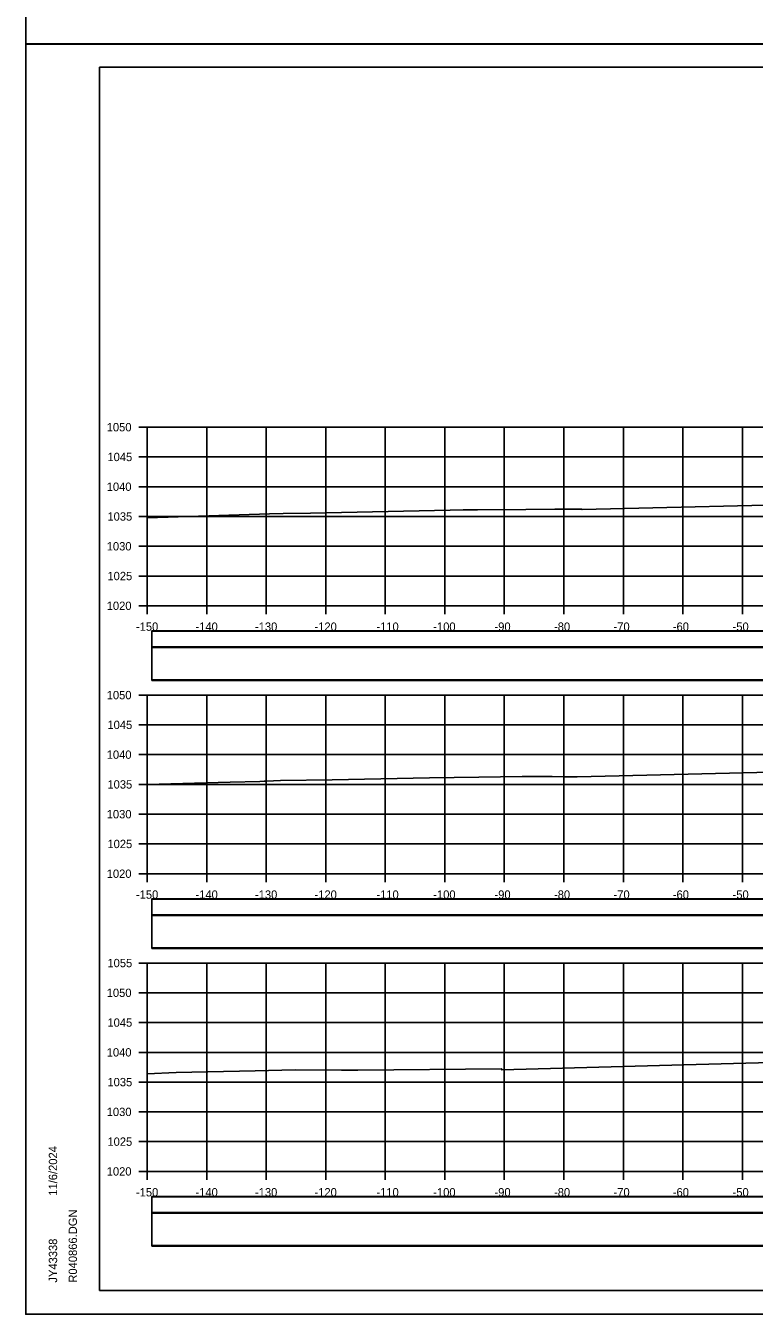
# Model space of a CAD drawing. Extents: x 1370565 to 1374448, y 301010 to 304637.
# Drawn here: x 1373198.4 to 1373320.8, y 301511.7 to 301728.1 of the extents above; entities that cross this region are included whole.
import ezdxf

# ---------------------------------------------------------------- set-up
doc = ezdxf.new("R2010")
doc.units = 0
for name, color, linetype in [('Default', 7, 'Continuous'), ('R_Axis', 7, 'Continuous'), ('R_Axis Annot', 7, 'Continuous'), ('R_Border', 7, 'Continuous'), ('R_Drive', 7, 'Continuous'), ('R_Exist Surface', 7, 'Continuous'), ('R_Grid', 7, 'Continuous'), ('R_No Plot', 7, 'Continuous')]:
    doc.layers.add(name, color=color, linetype=linetype)

msp = doc.modelspace()

# ---------------------------------------------------------------- linework, layer by layer
at = {"layer": 'Default'}
for points in [[(1373219.61, 301623.68), (1373518.02, 301623.68), (1373518.02, 301626.38), (1373219.61, 301626.38)], [(1373219.61, 301618.1), (1373518.02, 301618.1), (1373518.02, 301623.62), (1373219.61, 301623.62)], [(1373219.61, 301578.68), (1373518.02, 301578.68), (1373518.02, 301581.38), (1373219.61, 301581.38)], [(1373219.61, 301573.1), (1373518.02, 301573.1), (1373518.02, 301578.62), (1373219.61, 301578.62)], [(1373219.61, 301528.68), (1373518.02, 301528.68), (1373518.02, 301531.38), (1373219.61, 301531.38)], [(1373219.61, 301523.1), (1373518.02, 301523.1), (1373518.02, 301528.62), (1373219.61, 301528.62)]]:
    msp.add_lwpolyline(points, close=True, dxfattribs=at)
at = {"layer": 'R_Axis'}
for p, q in [((1373217.41, 301660.64), (1373218.81, 301660.64)), ((1373218.81, 301630.64), (1373218.81, 301660.64)), ((1373217.41, 301655.64), (1373218.81, 301655.64)), ((1373217.41, 301650.64), (1373218.81, 301650.64)), ((1373217.41, 301645.64), (1373218.81, 301645.64)), ((1373217.41, 301640.64), (1373218.81, 301640.64)), ((1373217.41, 301635.64), (1373218.81, 301635.64)), ((1373217.41, 301630.64), (1373218.81, 301630.64)), ((1373218.81, 301630.64), (1373518.81, 301630.64)), ((1373218.81, 301629.24), (1373218.81, 301630.64)), ((1373228.81, 301629.24), (1373228.81, 301630.64)), ((1373238.81, 301629.24), (1373238.81, 301630.64)), ((1373248.81, 301629.24), (1373248.81, 301630.64)), ((1373258.81, 301629.24), (1373258.81, 301630.64)), ((1373268.81, 301629.24), (1373268.81, 301630.64)), ((1373278.81, 301629.24), (1373278.81, 301630.64)), ((1373288.81, 301629.24), (1373288.81, 301630.64)), ((1373298.81, 301629.24), (1373298.81, 301630.64)), ((1373308.81, 301629.24), (1373308.81, 301630.64)), ((1373318.81, 301629.24), (1373318.81, 301630.64)), ((1373217.41, 301615.64), (1373218.81, 301615.64)), ((1373218.81, 301585.64), (1373218.81, 301615.64)), ((1373217.41, 301610.64), (1373218.81, 301610.64)), ((1373217.41, 301605.64), (1373218.81, 301605.64)), ((1373217.41, 301600.64), (1373218.81, 301600.64)), ((1373217.41, 301595.64), (1373218.81, 301595.64)), ((1373217.41, 301590.64), (1373218.81, 301590.64)), ((1373217.41, 301585.64), (1373218.81, 301585.64)), ((1373218.81, 301585.64), (1373518.81, 301585.64)), ((1373218.81, 301584.24), (1373218.81, 301585.64)), ((1373228.81, 301584.24), (1373228.81, 301585.64)), ((1373238.81, 301584.24), (1373238.81, 301585.64)), ((1373248.81, 301584.24), (1373248.81, 301585.64)), ((1373258.81, 301584.24), (1373258.81, 301585.64)), ((1373268.81, 301584.24), (1373268.81, 301585.64)), ((1373278.81, 301584.24), (1373278.81, 301585.64)), ((1373288.81, 301584.24), (1373288.81, 301585.64)), ((1373298.81, 301584.24), (1373298.81, 301585.64)), ((1373308.81, 301584.24), (1373308.81, 301585.64)), ((1373318.81, 301584.24), (1373318.81, 301585.64)), ((1373217.41, 301570.64), (1373218.81, 301570.64)), ((1373218.81, 301535.64), (1373218.81, 301570.64)), ((1373217.41, 301565.64), (1373218.81, 301565.64)), ((1373217.41, 301560.64), (1373218.81, 301560.64)), ((1373217.41, 301555.64), (1373218.81, 301555.64)), ((1373217.41, 301550.64), (1373218.81, 301550.64)), ((1373217.41, 301545.64), (1373218.81, 301545.64)), ((1373217.41, 301540.64), (1373218.81, 301540.64)), ((1373217.41, 301535.64), (1373218.81, 301535.64)), ((1373218.81, 301535.64), (1373518.81, 301535.64)), ((1373218.81, 301534.24), (1373218.81, 301535.64)), ((1373228.81, 301534.24), (1373228.81, 301535.64)), ((1373238.81, 301534.24), (1373238.81, 301535.64)), ((1373248.81, 301534.24), (1373248.81, 301535.64)), ((1373258.81, 301534.24), (1373258.81, 301535.64)), ((1373268.81, 301534.24), (1373268.81, 301535.64)), ((1373278.81, 301534.24), (1373278.81, 301535.64)), ((1373288.81, 301534.24), (1373288.81, 301535.64)), ((1373298.81, 301534.24), (1373298.81, 301535.64)), ((1373308.81, 301534.24), (1373308.81, 301535.64)), ((1373318.81, 301534.24), (1373318.81, 301535.64))]:
    msp.add_line(p, q, dxfattribs=at)
at = {"layer": 'R_Border'}
for p, q in [((1373210.81, 301721.1), (1373526.99, 301721.1)), ((1373210.81, 301515.64), (1373210.81, 301721.1)), ((1373210.81, 301515.64), (1373210.81, 301515.64)), ((1373526.99, 301515.64), (1373210.81, 301515.64))]:
    msp.add_line(p, q, dxfattribs=at)
at = {"layer": 'R_Drive'}
for points in [[(1373219.61, 301623.73), (1373518.02, 301623.73), (1373518.02, 301626.44), (1373219.61, 301626.44)], [(1373219.61, 301618.21), (1373518.02, 301618.21), (1373518.02, 301623.73), (1373219.61, 301623.73)], [(1373219.61, 301578.73), (1373518.02, 301578.73), (1373518.02, 301581.44), (1373219.61, 301581.44)], [(1373219.61, 301573.21), (1373518.02, 301573.21), (1373518.02, 301578.73), (1373219.61, 301578.73)], [(1373219.61, 301528.73), (1373518.02, 301528.73), (1373518.02, 301531.44), (1373219.61, 301531.44)], [(1373219.61, 301523.21), (1373518.02, 301523.21), (1373518.02, 301528.73), (1373219.61, 301528.73)]]:
    msp.add_lwpolyline(points, close=True, dxfattribs=at)
at = {"layer": 'R_Exist Surface'}
for points in [[(1373218.81, 301645.43), (1373222.34, 301645.52), (1373239.33, 301646.08), (1373241.64, 301646.13), (1373246.27, 301646.21), (1373269.73, 301646.72), (1373271.91, 301646.75), (1373274.32, 301646.77), (1373282.42, 301646.84), (1373287.32, 301646.87), (1373291.77, 301646.87), (1373291.79, 301646.86), (1373291.86, 301646.82), (1373334.63, 301647.81)], [(1373218.81, 301600.65), (1373232.75, 301601.01), (1373237.75, 301601.13), (1373238.47, 301601.21), (1373238.88, 301601.18), (1373241.23, 301601.3), (1373249.88, 301601.41), (1373266.26, 301601.77), (1373274.54, 301601.86), (1373281.79, 301601.96), (1373286.82, 301601.98), (1373288.89, 301601.92), (1373291.02, 301601.91), (1373298.13, 301602.08), (1373365.25, 301603.69)], [(1373218.81, 301552.03), (1373223.67, 301552.28), (1373236.94, 301552.55), (1373243.66, 301552.68), (1373251.46, 301552.65), (1373253.24, 301552.67), (1373254.21, 301552.67), (1373278.36, 301552.87), (1373278.36, 301552.84), (1373278.41, 301552.7), (1373308.96, 301553.53), (1373354.91, 301554.79)]]:
    msp.add_lwpolyline(points, dxfattribs=at)
at = {"layer": 'R_Grid'}
for p, q in [((1373218.81, 301660.64), (1373518.81, 301660.64)), ((1373218.81, 301630.64), (1373218.81, 301660.64)), ((1373228.81, 301630.64), (1373228.81, 301660.64)), ((1373238.81, 301630.64), (1373238.81, 301660.64)), ((1373248.81, 301630.64), (1373248.81, 301660.64)), ((1373258.81, 301630.64), (1373258.81, 301660.64)), ((1373268.81, 301630.64), (1373268.81, 301660.64)), ((1373278.81, 301630.64), (1373278.81, 301660.64)), ((1373288.81, 301630.64), (1373288.81, 301660.64)), ((1373298.81, 301630.64), (1373298.81, 301660.64)), ((1373308.81, 301630.64), (1373308.81, 301660.64)), ((1373318.81, 301630.64), (1373318.81, 301660.64)), ((1373218.81, 301655.64), (1373518.81, 301655.64)), ((1373218.81, 301650.64), (1373518.81, 301650.64)), ((1373218.81, 301645.64), (1373518.81, 301645.64)), ((1373218.81, 301640.64), (1373518.81, 301640.64)), ((1373218.81, 301635.64), (1373518.81, 301635.64)), ((1373218.81, 301630.64), (1373518.81, 301630.64)), ((1373218.81, 301615.64), (1373518.81, 301615.64)), ((1373218.81, 301585.64), (1373218.81, 301615.64)), ((1373228.81, 301585.64), (1373228.81, 301615.64)), ((1373238.81, 301585.64), (1373238.81, 301615.64)), ((1373248.81, 301585.64), (1373248.81, 301615.64)), ((1373258.81, 301585.64), (1373258.81, 301615.64)), ((1373268.81, 301585.64), (1373268.81, 301615.64)), ((1373278.81, 301585.64), (1373278.81, 301615.64)), ((1373288.81, 301585.64), (1373288.81, 301615.64)), ((1373298.81, 301585.64), (1373298.81, 301615.64)), ((1373308.81, 301585.64), (1373308.81, 301615.64)), ((1373318.81, 301585.64), (1373318.81, 301615.64)), ((1373218.81, 301610.64), (1373518.81, 301610.64)), ((1373218.81, 301605.64), (1373518.81, 301605.64)), ((1373218.81, 301600.64), (1373518.81, 301600.64)), ((1373218.81, 301595.64), (1373518.81, 301595.64)), ((1373218.81, 301590.64), (1373518.81, 301590.64)), ((1373218.81, 301585.64), (1373518.81, 301585.64)), ((1373218.81, 301570.64), (1373518.81, 301570.64)), ((1373218.81, 301535.64), (1373218.81, 301570.64)), ((1373228.81, 301535.64), (1373228.81, 301570.64)), ((1373238.81, 301535.64), (1373238.81, 301570.64)), ((1373248.81, 301535.64), (1373248.81, 301570.64)), ((1373258.81, 301535.64), (1373258.81, 301570.64)), ((1373268.81, 301535.64), (1373268.81, 301570.64)), ((1373278.81, 301535.64), (1373278.81, 301570.64)), ((1373288.81, 301535.64), (1373288.81, 301570.64)), ((1373298.81, 301535.64), (1373298.81, 301570.64)), ((1373308.81, 301535.64), (1373308.81, 301570.64)), ((1373318.81, 301535.64), (1373318.81, 301570.64)), ((1373218.81, 301565.64), (1373518.81, 301565.64)), ((1373218.81, 301560.64), (1373518.81, 301560.64)), ((1373218.81, 301555.64), (1373518.81, 301555.64)), ((1373218.81, 301550.64), (1373518.81, 301550.64)), ((1373218.81, 301545.64), (1373518.81, 301545.64)), ((1373218.81, 301540.64), (1373518.81, 301540.64)), ((1373218.81, 301535.64), (1373518.81, 301535.64))]:
    msp.add_line(p, q, dxfattribs=at)
at = {"layer": 'R_No Plot'}
for p, q in [((1373198.41, 301725), (1373531.75, 301725)), ((1373198.41, 301724.99), (1373531.75, 301724.99)), ((1373198.41, 301511.66), (1373531.75, 301511.66))]:
    msp.add_line(p, q, dxfattribs=at)
for points in [[(1373198.41, 301938.33), (1373531.75, 301938.33), (1373531.75, 301724.99), (1373198.41, 301724.99)], [(1373198.41, 301724.99), (1373531.75, 301724.99), (1373531.75, 301511.65), (1373198.41, 301511.65)], [(1373444.73, 301721.1), (1373464.35, 301721.1), (1373464.35, 301711.22), (1373480.47, 301711.22), (1373503.67, 301711.22), (1373503.67, 301686.88), (1373526.99, 301686.88), (1373526.99, 301515.64), (1373210.81, 301515.64), (1373210.81, 301721.1)]]:
    msp.add_lwpolyline(points, close=True, dxfattribs=at)

# ---------------------------------------------------------------- texts
at = {"layer": 'R_Axis Annot'}
for s, p in [('1050', (1373212.01, 301659.94)), ('1045', (1373212.13, 301654.94)), ('1040', (1373212.01, 301649.94)), ('1035', (1373212.13, 301644.94)), ('1030', (1373212.01, 301639.94)), ('1025', (1373212.13, 301634.94)), ('1020', (1373212.01, 301629.94)), ('-150', (1373216.92, 301626.44)), ('-140', (1373226.92, 301626.44)), ('-130', (1373236.92, 301626.44)), ('-120', (1373246.92, 301626.44)), ('-110', (1373257.32, 301626.44)), ('-100', (1373266.87, 301626.44)), ('-90', (1373277.16, 301626.44)), ('-80', (1373287.16, 301626.44)), ('-70', (1373297.16, 301626.44)), ('-60', (1373307.12, 301626.44)), ('-50', (1373317.16, 301626.44)), ('1050', (1373212.01, 301614.94)), ('1045', (1373212.13, 301609.94)), ('1040', (1373212.01, 301604.94)), ('1035', (1373212.13, 301599.94)), ('1030', (1373212.01, 301594.94)), ('1025', (1373212.13, 301589.94)), ('1020', (1373212.01, 301584.94)), ('-150', (1373216.92, 301581.44)), ('-140', (1373226.92, 301581.44)), ('-130', (1373236.92, 301581.44)), ('-120', (1373246.92, 301581.44)), ('-110', (1373257.32, 301581.44)), ('-100', (1373266.87, 301581.44)), ('-90', (1373277.16, 301581.44)), ('-80', (1373287.16, 301581.44)), ('-70', (1373297.16, 301581.44)), ('-60', (1373307.12, 301581.44)), ('-50', (1373317.16, 301581.44)), ('1055', (1373212.13, 301569.94)), ('1050', (1373212.01, 301564.94)), ('1045', (1373212.13, 301559.94)), ('1040', (1373212.01, 301554.94)), ('1035', (1373212.13, 301549.94)), ('1030', (1373212.01, 301544.94)), ('1025', (1373212.13, 301539.94)), ('1020', (1373212.01, 301534.94)), ('-150', (1373216.92, 301531.44)), ('-140', (1373226.92, 301531.44)), ('-130', (1373236.92, 301531.44)), ('-120', (1373246.92, 301531.44)), ('-110', (1373257.32, 301531.44)), ('-100', (1373266.87, 301531.44)), ('-90', (1373277.16, 301531.44)), ('-80', (1373287.16, 301531.44)), ('-70', (1373297.16, 301531.44)), ('-60', (1373307.12, 301531.44)), ('-50', (1373317.16, 301531.44))]:
    msp.add_text(s, height=1.4, dxfattribs=at).set_placement(p)
at = {"layer": 'R_Border'}
for s, p in [('11/6/2024', (1373203.68, 301531.56)), ('R040866.DGN', (1373207.01, 301516.96)), ('JY43338', (1373203.68, 301516.96))]:
    msp.add_text(s, height=1.4, rotation=90, dxfattribs=at).set_placement(p)

doc.saveas('drawing.dxf')
